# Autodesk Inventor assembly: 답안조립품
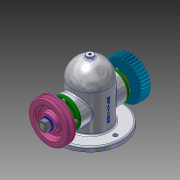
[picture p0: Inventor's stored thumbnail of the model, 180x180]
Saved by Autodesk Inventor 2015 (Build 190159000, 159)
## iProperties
Created: 2019-11
Part Number: 답안조립품
Document SubType Name: Assembly
Designer: Lineart
Author: Lineart
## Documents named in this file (14)
- C:\Users\Lineart\Desktop\491104V1012\답안조립품.iam
- C:\Users\Lineart\Desktop\491104V1012\본체.ipt
- C:\Users\Lineart\Desktop\491104V1012\축.ipt
- C:\Users\Lineart\Desktop\491104V1012\베어링 6203.ipt
- C:\Users\Lineart\Desktop\491104V1012\부시.ipt
- C:\Users\Lineart\Desktop\491104V1012\커버.ipt
- C:\Users\Lineart\Desktop\491104V1012\오일 실 26 38 8.ipt
- C:\Users\Lineart\Desktop\491104V1012\키 5x5x12.ipt
- C:\Users\Lineart\Desktop\491104V1012\너트 M12x1.25.ipt
- C:\Users\Lineart\Desktop\491104V1012\스퍼기어.ipt
- C:\Users\Lineart\Desktop\491104V1012\와셔 12x24.ipt
- C:\Users\Lineart\Desktop\491104V1012\V-벨트풀리.ipt
- V-벨트풀리.ipt
- C:\Users\Lineart\Desktop\491104V1012\볼트 M4.ipt
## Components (1 placed, 1 different names)
1. V-벨트풀리:1 — 각도:3
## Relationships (1: Angle 1)
- 각도:3 [Angle]: V-벨트풀리:1
